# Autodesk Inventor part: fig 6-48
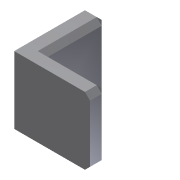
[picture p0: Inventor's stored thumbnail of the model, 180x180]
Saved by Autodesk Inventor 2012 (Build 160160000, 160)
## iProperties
Created: 2009-09
Part Number: fig 6-48
Document SubType Name: Modeling
Designer: Sham
Density: 1 g/cm^3
Material: Default
Author: Sham
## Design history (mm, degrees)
sketch "Sketch1"
  geometry: L1 (1.789, 30)-(1.789, -5); L2 (1.789, -5)-(36.789, -5); L3 (36.789, -5)-(36.789, -15); L4 (36.789, -15)-(-8.211, -15); L5 (-8.211, -15)-(-8.211, 30); L6 (-8.211, 30)-(1.789, 30)
  constraints: 12 end point, 6 perpendicular
  dimensions: "d0" = 10 distance of L5.end L1.start; "d1" = 35 distance of L1.start L1.end; "d2" = 45 distance of L3.end L4.end; "d3" = 10 distance of L2.end L3.end (derived)
extrude "Extrusion1" new body sketch "Sketch1" distance "d4" = 40; taper "d5" = 0 deg
chamfer "Chamfer1" distance "d6" = 3; stored, may be unused: second distance "d7" = 2, angle "d8" = 45 deg
body "Solid1"
other parameters: "d1" = 35
